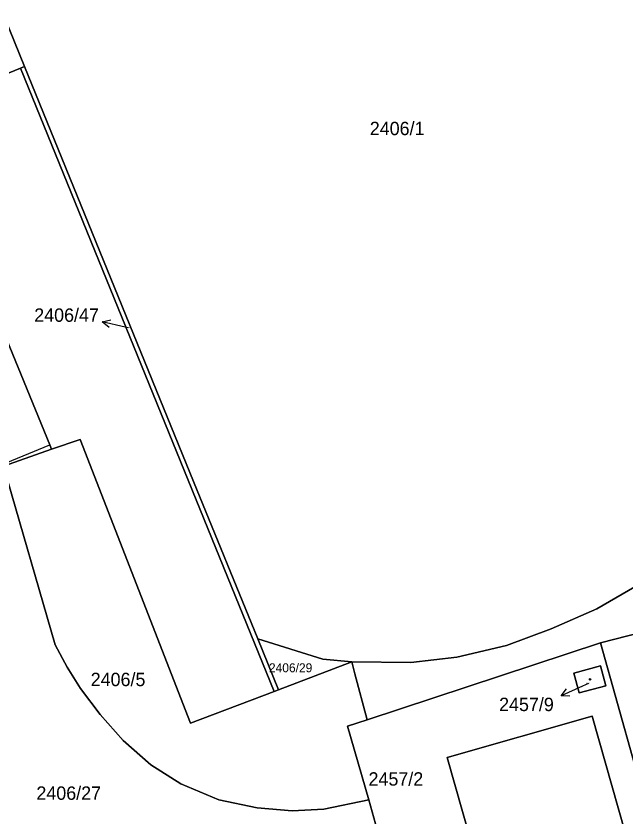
# Model space of a CAD drawing. Extents: x -596233 to -595156, y -1161235 to -1159375.
# Drawn here: x -595617.7 to -595540.2, y -1160573.8 to -1160472 of the extents above; entities that cross this region are included whole.
import ezdxf

# ---------------------------------------------------------------- set-up
doc = ezdxf.new("R2010")
doc.units = 0
for name, color, linetype in [('KN_CAR_KR', 7, 'Continuous'), ('KN_KULTURY', 7, 'Continuous'), ('KN_PARC_CIS_POM', 7, 'Continuous'), ('KN_PARC_CIS_POZ', 7, 'Continuous'), ('KN_PARC_CIS_STAV', 7, 'Continuous'), ('KN_PARC_PLOCHA', 7, 'Continuous'), ('PARC_C_SIPKA', 7, 'Continuous'), ('parcely_l', 7, 'Continuous')]:
    doc.layers.add(name, color=color, linetype=linetype)

msp = doc.modelspace()

# ---------------------------------------------------------------- linework, layer by layer
at = {"layer": 'KN_CAR_KR'}
msp.add_lwpolyline([(-595624.37, -1160531.02), (-595613.46, -1160526.53)], dxfattribs=at)
at = {"layer": 'KN_KULTURY'}
for radius in [0.09, 0.0398]:
    msp.add_circle((-595544.81, -1160556.31), radius, dxfattribs=at)
at = {"layer": 'KN_PARC_PLOCHA'}
for points in [[(-595626.1, -1160455.3), (-595625.45, -1160456.9), (-595616.66, -1160478.48), (-595617.18, -1160478.69), (-595620.8, -1160480.15), (-595623.51, -1160473.69), (-595629.82, -1160476.24), (-595630.21, -1160475.32), (-595644.71, -1160440.78), (-595633.73, -1160436.58)], [(-595587.04, -1160551.18), (-595584.41, -1160557.64), (-595584.93, -1160557.84), (-595617.18, -1160478.69), (-595616.66, -1160478.48), (-595595.2, -1160531.16)], [(-595613.23, -1160527.08), (-595619.32, -1160529.23), (-595624.37, -1160531.02), (-595637.93, -1160498.01), (-595626.98, -1160493.54), (-595613.46, -1160526.53)], [(-595584.93, -1160557.84), (-595584.41, -1160557.64), (-595575.09, -1160554.1), (-595574.69, -1160555.59), (-595573.13, -1160561.44), (-595575.61, -1160562.26), (-595572.93, -1160571.61), (-595578.64, -1160572.79), (-595582.64, -1160573), (-595587.1, -1160572.64), (-595591.96, -1160571.6), (-595596.8, -1160569.58), (-595600.61, -1160567.16), (-595604.12, -1160564.06), (-595607.05, -1160560.78), (-595609.53, -1160557.46), (-595611.25, -1160554.74), (-595612.78, -1160551.91), (-595619.32, -1160529.23), (-595613.23, -1160527.08), (-595609.6, -1160525.83), (-595595.56, -1160561.87)], [(-595505.53, -1160541.68), (-595512.56, -1160543.76), (-595543.49, -1160551.67), (-595573.13, -1160561.44), (-595574.69, -1160555.59), (-595575.09, -1160554.1), (-595567.58, -1160554.18), (-595561.74, -1160553.47), (-595555.43, -1160552), (-595549.75, -1160549.87), (-595543.95, -1160547.34), (-595539.12, -1160544.54), (-595535.58, -1160541.75), (-595531.82, -1160538.27), (-595508.65, -1160530.5)], [(-595509.87, -1160553.41), (-595516.78, -1160555.43), (-595523.81, -1160557.64), (-595522.33, -1160562.38), (-595539.15, -1160567.09), (-595543.49, -1160551.67), (-595512.56, -1160543.76)], [(-595575.09, -1160554.1), (-595584.41, -1160557.64), (-595587.04, -1160551.18), (-595578.75, -1160553.74)], [(-595539.15, -1160567.09), (-595534.48, -1160583.61), (-595537.85, -1160584.57), (-595544.53, -1160560.99), (-595562.95, -1160566.22), (-595554.12, -1160597.39), (-595532.33, -1160591.21), (-595530.87, -1160596.35), (-595555.12, -1160603.52), (-595557.96, -1160599.9), (-595564.92, -1160577.3), (-595570.83, -1160579.04), (-595571.23, -1160577.72), (-595572.93, -1160571.61), (-595575.61, -1160562.26), (-595573.13, -1160561.44), (-595543.49, -1160551.67)], [(-595542.79, -1160557.11), (-595543.47, -1160554.6), (-595546.87, -1160555.52), (-595546.19, -1160558.03)], [(-595542.79, -1160557.11), (-595546.19, -1160558.03), (-595546.87, -1160555.52), (-595543.47, -1160554.6)], [(-595534.48, -1160583.61), (-595532.33, -1160591.21), (-595554.12, -1160597.39), (-595562.95, -1160566.22), (-595544.53, -1160560.99), (-595537.85, -1160584.57)]]:
    msp.add_lwpolyline(points, close=True, dxfattribs=at)
for points in [[(-595528.45, -1160470.12), (-595525.61, -1160478.19), (-595515.77, -1160474.76), (-595512.47, -1160482.74), (-595508.84, -1160491.32), (-595501.74, -1160528.22), (-595508.65, -1160530.5), (-595531.82, -1160538.27), (-595535.58, -1160541.75), (-595539.12, -1160544.54), (-595543.95, -1160547.34), (-595549.75, -1160549.87), (-595555.43, -1160552), (-595561.74, -1160553.47), (-595567.58, -1160554.18), (-595575.09, -1160554.1), (-595578.75, -1160553.74), (-595587.04, -1160551.18), (-595595.2, -1160531.16), (-595616.66, -1160478.48), (-595625.45, -1160456.9)], [(-595620.8, -1160480.15), (-595617.18, -1160478.69), (-595584.93, -1160557.84), (-595595.56, -1160561.87), (-595609.6, -1160525.83), (-595613.23, -1160527.08), (-595613.46, -1160526.53), (-595626.98, -1160493.54)], [(-595619.32, -1160529.23), (-595612.78, -1160551.91), (-595611.25, -1160554.74), (-595609.53, -1160557.46), (-595607.05, -1160560.78), (-595604.12, -1160564.06), (-595600.61, -1160567.16), (-595596.8, -1160569.58), (-595591.96, -1160571.6), (-595587.1, -1160572.64), (-595582.64, -1160573), (-595578.64, -1160572.79), (-595572.93, -1160571.61), (-595571.23, -1160577.72), (-595574.44, -1160580.1), (-595577.71, -1160581.13), (-595594.76, -1160586.57), (-595601.37, -1160588.66), (-595608.07, -1160590.8), (-595614.73, -1160592.92), (-595617.38, -1160593.76), (-595619.68, -1160586.46)]]:
    msp.add_lwpolyline(points, dxfattribs=at)
at = {"layer": 'PARC_C_SIPKA'}
for points in [[(-595605.921, -1160511.5981), (-595606.7866, -1160510.8905), (-595605.7011, -1160510.6225)], [(-595603.46, -1160511.64), (-595603.86, -1160511.55), (-595606.7866, -1160510.8905)], [(-595544.99, -1160556.84), (-595545.75, -1160557.18), (-595548.493, -1160558.3948)], [(-595547.3762, -1160558.447), (-595548.493, -1160558.3948), (-595547.7812, -1160557.5327)]]:
    msp.add_lwpolyline(points, dxfattribs=at)
at = {"layer": 'parcely_l'}
for points in [[(-595625.45, -1160456.9), (-595616.66, -1160478.48)], [(-595617.18, -1160478.69), (-595620.8, -1160480.15)], [(-595617.18, -1160478.69), (-595616.66, -1160478.48)], [(-595584.93, -1160557.84), (-595617.18, -1160478.69)], [(-595616.66, -1160478.48), (-595595.2, -1160531.16), (-595587.04, -1160551.18)], [(-595613.23, -1160527.08), (-595613.46, -1160526.53), (-595626.98, -1160493.54), (-595637.93, -1160498.01), (-595624.37, -1160531.02)], [(-595613.23, -1160527.08), (-595609.6, -1160525.83), (-595595.56, -1160561.87), (-595584.93, -1160557.84)], [(-595619.32, -1160529.23), (-595613.23, -1160527.08)], [(-595572.93, -1160571.61), (-595578.64, -1160572.79), (-595582.64, -1160573), (-595587.1, -1160572.64), (-595591.96, -1160571.6), (-595596.8, -1160569.58), (-595600.61, -1160567.16), (-595604.12, -1160564.06), (-595607.05, -1160560.78), (-595609.53, -1160557.46), (-595611.25, -1160554.74), (-595612.78, -1160551.91), (-595619.32, -1160529.23)], [(-595575.09, -1160554.1), (-595567.58, -1160554.18), (-595561.74, -1160553.47), (-595555.43, -1160552), (-595549.75, -1160549.87), (-595543.95, -1160547.34), (-595539.12, -1160544.54), (-595535.58, -1160541.75), (-595531.82, -1160538.27), (-595508.65, -1160530.5)], [(-595512.56, -1160543.76), (-595543.49, -1160551.67)], [(-595587.04, -1160551.18), (-595584.41, -1160557.64)], [(-595587.04, -1160551.18), (-595578.75, -1160553.74), (-595575.09, -1160554.1)], [(-595543.49, -1160551.67), (-595573.13, -1160561.44)], [(-595543.49, -1160551.67), (-595539.15, -1160567.09)], [(-595575.09, -1160554.1), (-595584.41, -1160557.64)], [(-595575.09, -1160554.1), (-595574.69, -1160555.59), (-595573.13, -1160561.44)], [(-595542.79, -1160557.11), (-595546.19, -1160558.03), (-595546.87, -1160555.52), (-595543.47, -1160554.6), (-595542.79, -1160557.11)], [(-595584.41, -1160557.64), (-595584.93, -1160557.84)], [(-595573.13, -1160561.44), (-595575.61, -1160562.26), (-595572.93, -1160571.61)], [(-595532.33, -1160591.21), (-595554.12, -1160597.39), (-595562.95, -1160566.22), (-595544.53, -1160560.99), (-595537.85, -1160584.57), (-595534.48, -1160583.61)], [(-595572.93, -1160571.61), (-595571.23, -1160577.72)]]:
    msp.add_lwpolyline(points, dxfattribs=at)

# ---------------------------------------------------------------- texts
at = {"layer": 'KN_PARC_CIS_POM'}
for s, p in [('2406/47', (-595603.6183, -1160511.64)), ('2457/9', (-595545.2733, -1160556.84))]:
    msp.add_text(s, height=0.1, dxfattribs=at).set_placement(p)
at = {"layer": 'KN_PARC_CIS_POZ'}
for s, height, p in [('2406/1', 1.7, (-595572.7966, -1160487.18)), ('2406/47', 1.7, (-595615.4316, -1160510.89)), ('2406/29', 1.14, (-595585.61, -1160555.41)), ('2406/5', 1.7, (-595608.2566, -1160557.17)), ('2457/2', 1.7, (-595572.9566, -1160569.81)), ('2406/27', 1.7, (-595615.1566, -1160571.61))]:
    msp.add_text(s, height=height, dxfattribs=at).set_placement(p)
at = {"layer": 'KN_PARC_CIS_STAV'}
msp.add_text('2457/9', height=1.7, dxfattribs=at).set_placement((-595556.3666, -1160560.34))

doc.saveas('drawing.dxf')
